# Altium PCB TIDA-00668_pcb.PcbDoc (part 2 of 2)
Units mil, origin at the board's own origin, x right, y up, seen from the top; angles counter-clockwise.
Board outline 2510.03 x 1760.03 mil, 4 copper layers (Component Side 1, Signal Layer 2, Signal Layer 3, Solder Side 4), stack 60.634 mil thick; 105 components, 46 nets, 336 pads, 4 vias.
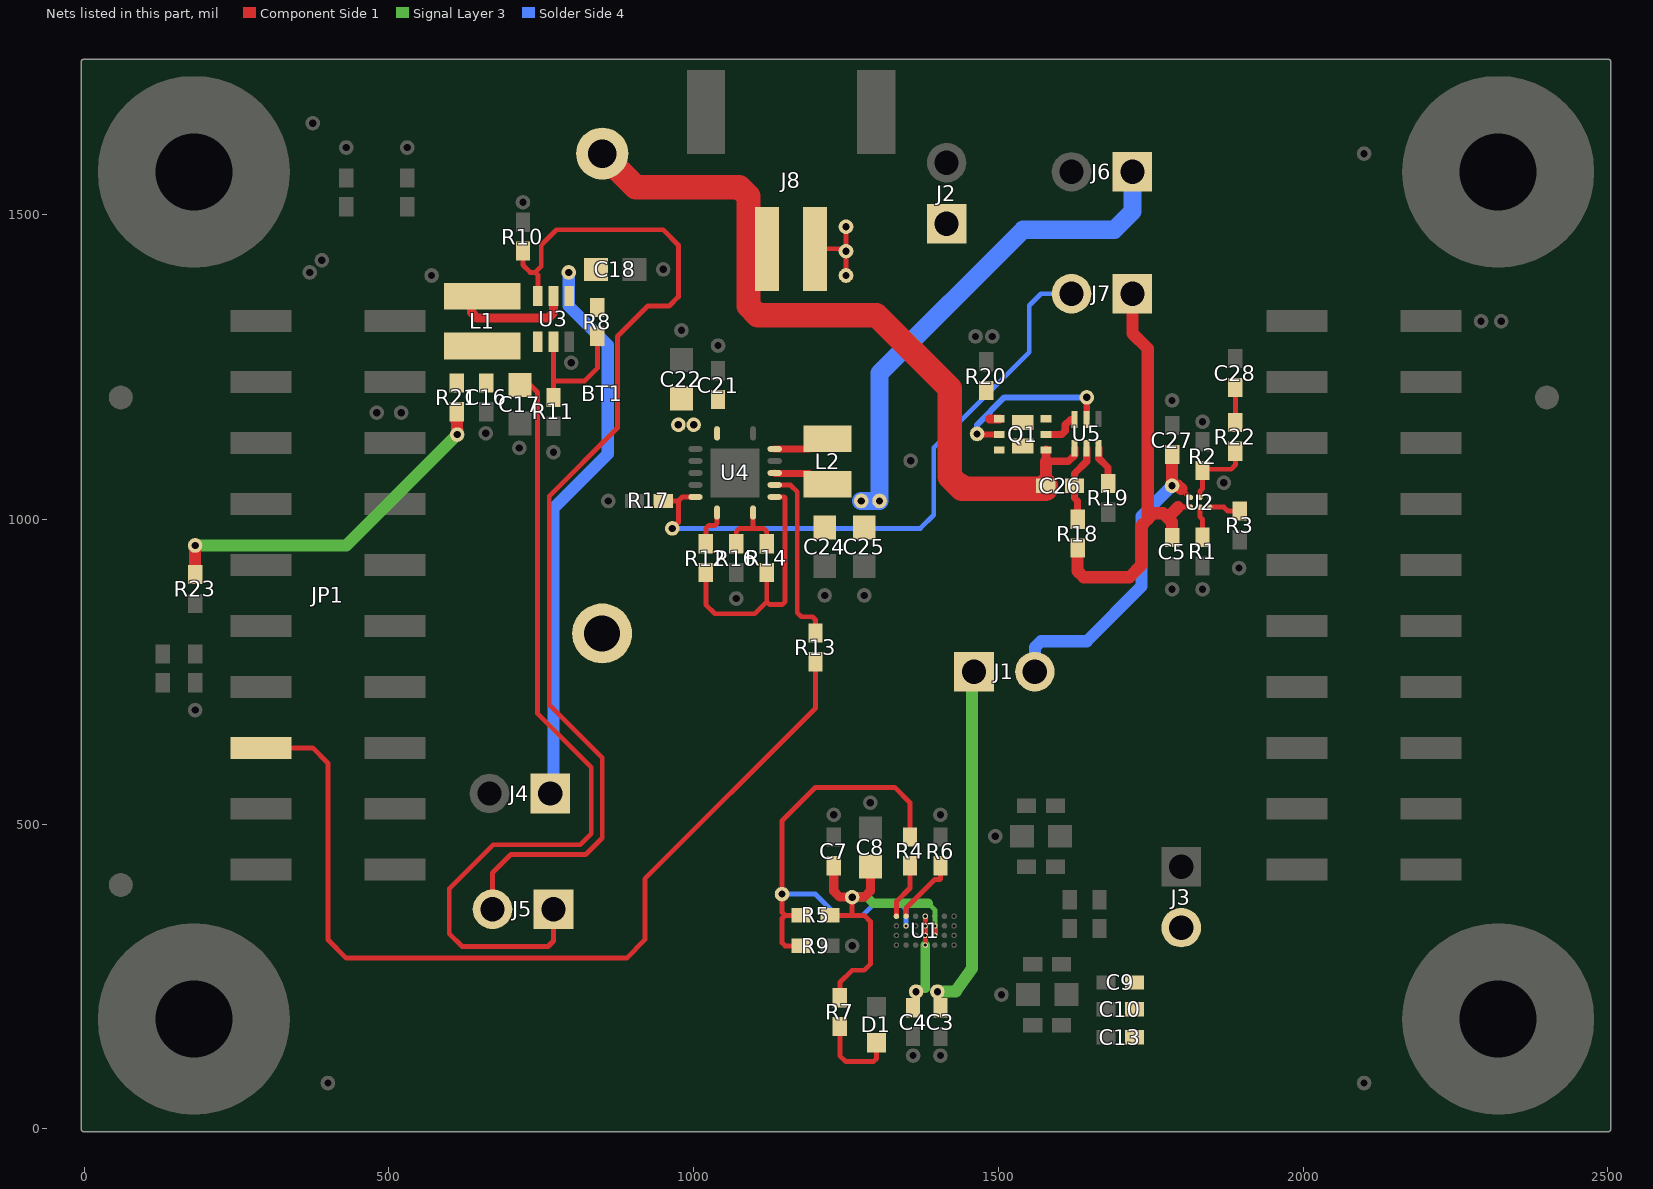
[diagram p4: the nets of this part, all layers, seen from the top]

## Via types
v1: diameter 19.68, hole 7.87, Component Side 1 to Solder Side 4, 4 vias

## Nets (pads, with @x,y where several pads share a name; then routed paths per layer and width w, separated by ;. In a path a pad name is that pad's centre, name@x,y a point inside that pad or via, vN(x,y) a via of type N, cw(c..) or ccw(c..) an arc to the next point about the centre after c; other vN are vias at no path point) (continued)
NetBT1_1: BT1.1 C5.1 C21.1 C22.1 J2.1 J7.1 J8.1 pad.0@182,957 pad.0@612,1139 pad.0@975,1155 pad.0@1000,1155 pad.0@1250,1400 pad.0@1250,1440 pad.0@1250,1480 R18.2 R21.1 R23.2 U2.A1 U4.1 | length 1457.1
  Component Side 1 w8: J8.1@1199.37,1443.86 1243.86,1443.86 pad.0@1250,1440 ; pad.0@1250,1400 pad.0@1250,1440 ; pad.0@1250,1480 pad.0@1250,1440 ; 1795,1020 U2.A1@1815,1020
  Component Side 1 w20: R23.2@182,909.24 pad.0@182,957 ; R21.1@611,1176.38 pad.0@612,1139 ; R18.2@1630,952.76 1630,915 1640,905 1715,905 1735,925 1735,990 1745,1000 ; J7.1@1720,1370 1720,1305 1745,1280 1745,1000 ; C5.1@1785,970 1785,995 1777.5,1002.5 ; 1795,1020 1777.5,1002.5 ; 1745,1000 1755,1010 1770,1010 1777.5,1002.5
  Signal Layer 3 w20: pad.0@182,957 430,957 pad.0@612,1139
NetBT1_2: BT1.2 C26.2 J8.2 Q1.4 U5.4 | length 1268.6
  Component Side 1 w12: 1578.39,1095 1615,1095 1625.32,1105.32 U5.4@1625.32,1116.38
  Component Side 1 w15: C26.2@1577.76,1055 C26.2@1578.39,1055.63 ; 1578.39,1095 Q1.4@1578.39,1113.62
  Component Side 1 w20: C26.2@1578.39,1055.63 1578.39,1095
  Component Side 1 w40: BT1.2@850,1600 905,1545 1075,1545 1090,1530 1090,1350 1105,1335 1300,1335 1420,1215 1420,1070 1439.22,1050.78 ; 1438.23,1055 1439.23,1054 ; 1440,1050 C26.2@1577.53,1050 ; C26.2@1576.76,1054 C26.2@1577.76,1055
NetC3_1: C3.1 C4.1 J1.1 pad.0@1365,225 pad.0@1380,317.13 pad.0@1380,332.9 pad.0@1380,348.65 pad.0@1380.01,301.37 pad.0@1400,225 U1.D1 U1.D2 U1.D3 U1.D4 | length 757.9
  Component Side 1 w8: U1.D4@1380,301.38 U1.D3@1380,317.13 U1.D2@1380,332.87 ; U1.D2@1380,332.87 U1.D1@1380,348.62
  Signal Layer 3 w8: pad.0@1365,225 1380,230 ; 1380,290 pad.0@1380,317.13 pad.0@1380,332.9 pad.0@1380,348.65
  Signal Layer 3 w15: 1380,230 pad.0@1380.01,301.37
  Signal Layer 3 w20: pad.0@1400,225 1430,225 1457,263 1457,747 J1.1@1460,750
NetC9_2: C9.2 C10.2 C13.2 J3.2
NetC16_1: C16.1 C17.1 J5.1 L1.1 R21.2 U3.1 | length 1374.3
  Component Side 1 w8: C17.1@715,1220.5 731.5,1220.5 744,1208 744,681 832,593 832,484 814,466 671,466 599,394 599,320 620,299 761,299 770,308 J5.1@770,360
NetC18_1: C18.1 J4.1 pad.0@795,1405 R8.2 U3.4 | length 918.4
  Solder Side 4 w20: J4.1@770,550 770,1018 859,1107 859,1286 795,1350 pad.0@795,1405
NetC24_1: C24.1 C25.1 J6.1 L2.2 pad.0@1275,1030 pad.0@1305,1030 U4.11 | length 914
  Component Side 1 w12: U4.11@1132.96,1076 1133.96,1075 1190,1075 1195,1070 L2.2@1195,1050
  Solder Side 4 w30: pad.0@1275,1030 pad.0@1305,1030 1305,1239.55 1540.45,1475 1690,1475 1720,1505 J6.1@1720,1570
NetC26_1: C26.1 R18.1 U5.5 | length 126.7
  Component Side 1 w12: R18.1@1630,1000 1630,1030 1625,1035 C26.1@1625,1055 1625,1075 1645,1095 U5.5@1645,1116.38
NetC27_1: C27.1 J1.2 pad.0@1785,1055 U2.A2 | length 536.5
  Component Side 1 w8: 1800,1050 1814.25,1035.75 U2.A2@1815,1035.75
  Component Side 1 w20: C27.1@1785,1111.38 pad.0@1785,1055 1795,1055 1800,1050
  Solder Side 4 w20: J1.2@1560,750 1560,790 1570,800 1645,800 1735,890 1735,1005 pad.0@1785,1055
NetC28_1: C28.1 R22.1 | length 57.4
  Component Side 1 w8: R22.1@1889,1159 C28.1@1889,1216.38
NetD1_1: D1.1 R7.1 | length 139.9
  Component Side 1 w8: R7.1@1240,167.76 1240,120 1250,110 1295,110 1300,115 D1.1@1300,140.94
NetJ5_2: J5.2 R10.2 U3.6 | length 1764.8
  Component Side 1 w8: J5.2@670,360 670,420 700,450 823,450 850,477 850,609 763,696 763,1038 875,1150 875,1300 925,1350 960,1350 975,1365 975,1450 950,1475 775,1475 750,1450 750,1415 740,1405 ; R10.2@720,1440 720,1417 731,1406 731,1405 740,1405 ; U3.6@744.41,1366.4 744.41,1400.59 740,1405
NetJ7_2: J7.2 pad.0@965,985 R17.2 U4.6 | length 1028.9
  Component Side 1 w8: R17.2@950,1030 975,1030 ; pad.0@965,985 975,995 975,1030 ; U4.6@1003.04,1036.63 981.63,1036.63 975,1030
  Solder Side 4 w8: pad.0@965,985 1372,985 1394,1007 1394,1117.5 1550.75,1274.25 1550.75,1350.75 1570,1370 J7.2@1620,1370
NetL1_2: L1.2 U3.5 | length 195.8
  Component Side 1 w15: L1.2@635.59,1365.76 635.59,1339.41 645,1330 761,1330 770,1339 U3.5@770,1366.4
NetL2_1: L2.1 U4.13 | length 85.5
  Component Side 1 w12: U4.13@1132.96,1115.37 1189.63,1115.37 1195,1120.73 L2.1@1195,1142
NetQ1_1: Q1.1 R20.2 | length 16.4
  Component Side 1 w15: 1485.2,1164.8 Q1.1@1501.61,1164.8
NetQ1_2: pad.0@1465,1140 pad.0@1645,1200 Q1.2 U5.2 | length 286.7
  Component Side 1 w10: pad.0@1465,1140 1474.21,1139.21 Q1.2@1501.61,1139.21 ; U5.2@1645,1163.62 pad.0@1645,1200
  Solder Side 4 w10: pad.0@1465,1140 1465,1155 1510,1200 pad.0@1645,1200
NetQ1_3: Q1.3 Q1.6 Q1.7 Q1.8
NetQ1_5: Q1.5 U5.3 | length 56.2
  Component Side 1 w12: Q1.5@1578.39,1139.21 1604.21,1139.21 1610,1145 1610,1155 1618.62,1163.62
NetR1_2: R1.2 U2.B1 | length 51.8
  Component Side 1 w8: U2.B1@1830.75,1020 1830.75,1004.25 1835,1000 R1.2@1835,970
NetR2_2: R2.2 R22.2 U2.B2 | length 127.7
  Component Side 1 w8: U2.B2@1830.75,1035.75 1830.75,1045.75 1835,1050 R2.2@1835,1080 1835,1082 1882,1082 1889,1089 R22.2@1889,1111.76
NetR3_2: R3.2 U2.C1 | length 51.1
  Component Side 1 w8: U2.C1@1846.5,1020 1870,1020 1876.38,1013.62 R3.2@1895,1013.62
NetR4_1: pad.0@1145,385 pad.0@1348.5,332.85 R4.1 R5.1 R9.2 U1.F2 | length 819
  Component Side 1 w8: R9.2@1176.38,300 1150,300 1145,305 1145,345 1150,350 ; R5.1@1176.38,350 1150,350 ; R4.1@1355,478.62 1355,535 1330,560 1200,560 1145,505 pad.0@1145,385 1145,355 1150,350
  Solder Side 4 w8: pad.0@1145,385 1200,385 1235,350 1277.5,350 1295,367.5 1341,367.5 1348.5,360 pad.0@1348.5,332.85
NetR4_2: R4.2 U1.G1 | length 92
  Component Side 1 w8: U1.G1@1332.76,348.62 1332.76,372.76 1355,395 R4.2@1355,431.38
NetR8_1: R8.1 R11.2 U3.2 | length 224.7
  Component Side 1 w8: R11.2@770,1200 770,1227 ; U3.2@770,1291.6 770,1227 ; R8.1@842,1300.38 842,1248 821,1227 770,1227
NetR12_1: R12.1 R14.2 U4.9 | length 436.9
  Component Side 1 w8: R12.1@1020,912.76 1020,860 1035,845 1100,845 1120,865 ; R14.2@1120,912.76 1120,865 ; U4.9@1132.96,1036.63 1148.37,1036.63 1150,1035 1150,865 1145,860 1125,860 1120,865
NetR12_2: R12.2 U4.7 | length 64.5
  Component Side 1 w8: R12.2@1020,960 1020,985 1025,990 1035,990 1038.47,993.47 U4.7@1038.47,1011.04
NetR13_2: R13.2 U4.10 | length 296.1
  Component Side 1 w8: U4.10@1132.96,1056.31 1158.69,1056.31 1170,1045 1170,846.93 1176.93,840 1195,840 1200,835 R13.2@1200,813.62
NetR14_1: R14.1 R16.2 U4.8 | length 117.7
  Component Side 1 w8: R16.2@1070,960 1070,980 1075,985 1115,985 1120,980 R14.1@1120,960 ; 1097.52,987.52 U4.8@1097.52,1011.04
NetR19_2: R19.2 U5.6 | length 64.1
  Component Side 1 w12: U5.6@1664.68,1116.38 1664.68,1100.32 1680,1085 R19.2@1680,1058.62
RECT: C7.1 C8.1 pad.0@1260,380 pad.0@1395.75,317.1 pad.0@1395.75,332.85 R5.2 R7.2 U1.C2 U1.C3 | length 609.9
  Component Side 1 w8: R5.2@1223.62,350 1260,350 ; R7.2@1240,215 1240,240 1260,260 1280,260 1290,270 1290,340 1280,350 1260,350 ; pad.0@1260,380 1260,350 ; U1.C3@1395.75,317.13 U1.C2@1395.75,332.87
  Component Side 1 w15: C7.1@1230,431.38 1230,390 1240,380 pad.0@1260,380 1280,380 1290,390 C8.1@1290,430
  Signal Layer 3 w8: 1385,370 1395.75,359.25 pad.0@1395.75,332.85 pad.0@1395.75,317.1
  Signal Layer 3 w15: pad.0@1260,380 1285,380 1295,370 1385,370
TS: R6.2 U1.F1 | length 110.9
  Component Side 1 w8: U1.F1@1348.5,348.62 1348.5,361.61 1396.05,409.15 1404.15,409.15 1405,410 R6.2@1405,431.38
VIN_OK: JP1.15 R13.1 | length 1527.6
  Component Side 1 w8: JP1.15@290,625 375,625 400,600 400,310 430,280 890,280 920,310 920,410 1200,690 R13.1@1200,766.38
pads on no net: FID1.1 FID2.1 FID3.1 H1.1 H2.1 H3.1 H4.1 H5.1 H6.1 H7.1 H8.1 HS5.0 HS6.0 HS7.0 HS8.0 J8.M1 J8.M2 JP1.3 JP1.5 JP1.6 JP1.7 JP1.8 JP1.9 JP1.10 JP1.12 JP1.13 JP1.14 JP1.16 JP1.17 JP1.18 JP1.19 JP1.20 JP2.1 JP2.3 JP2.4 JP2.5 JP2.6 JP2.7 JP2.8 JP2.9 JP2.10 JP2.11 JP2.12 JP2.13 JP2.14 JP2.15 JP2.16 JP2.17 JP2.18 JP2.19 JP2.20 SH-J1.0 SH-J4.0 SH-J5.0 SH-J6.0 SH-J7.0 U1.F3 U4.2 U4.3 U4.4 U4.14 U5.1

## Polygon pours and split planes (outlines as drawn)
GND on Signal Layer 2 "Signal Layer 2-GND" (solid, remove dead copper, pour order 2): 25,25 25,1725 2475,1725 2475,25 25,25
GND on Signal Layer 3 "Signal Layer 3-gnd" (solid, remove dead copper, pour order 8): 25,25 2475,25 2475,1725 25,1725 25,25
NetBT1_1 on Signal Layer 3 "Signal Layer 3-BT1_1" (solid, remove dead copper, pour order 4): 1800,1625 575,1625 575,275 925,275 925,550 1050,675 1800,675 1800,1625
GND on Component Side 1 "Component Side 1-gnd" (solid, remove dead copper, pour order 6): 25,25 2475,25 2475,1725 25,1725 25,25
GND on Solder Side 4 "Solder Side 4-gnd" (solid, remove dead copper, pour order 10): 2475,25 2475,1725 25,1725 25,25

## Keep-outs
Keep-Out Layer:
  lines w10: 0,0 2500,0 ; 0,0 0,1750 ; 0,0 2500,0 ; 0,1750 2500,1750 ; 0,1750 2500,1750 ; 2500,0 2500,1750 ; 2500,0 2500,1750
  text ".Layer_Name" at 577,-858.49 h60

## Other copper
Component Side 1:
  rectangle net GND: 787,1242 819,1310
  rectangle net NetC16_1: 590,1208 744,1309
  rectangle net NetQ1_5: 1604,1150 1630,1178
  rectangle net NetBT1_2: 1568,1044 1597,1121
  rectangle net GND: 1441.78,1245 1515,1325
  rectangle net NetQ1_1: 1465,1160 1510,1225
  rectangle net NetQ1_3: 1550,1160 1595,1235
  rectangle net NetQ1_3: 1450,1080 1525,1120
  rectangle net NetQ1_3: 1520,1080 1560,1235
  rectangle net NetL1_2: 592,1323 727,1388
  rectangle net NetBT1_1: 1180,1375 1275,1515
  rectangle net NetBT1_2: 1035,1375 1135,1515
  rectangle net NetC24_1: 1180,965 1355,1057.45
  rectangle net GND: 1190,850 1350,940
  rectangle net NetC18_1: 788,1355 860,1425
  rectangle net NetBT1_1: 960,1140 1055,1220
  rectangle net GND: 1350,110 1415,165
  rectangle net NetC3_1: 1350,185 1415,240
  rectangle net AC1: 1590,130 1690,345
  rectangle net NetC9_2: 1765,215 1835,360
  rectangle net NetC9_2: 1710,125 1835,265
  rectangle net AC2: 1700,395 1840,465
  rectangle net AC2: 1580,360 1720,550
  text "TI" at 2440,896 h60 r90
  text ".CopyrightYear" at 2440,620 h60 r90
  text "©" at 2445,510 h105 r90
  text ".Layer_Name" at 577,-858.49 h60
Signal Layer 3:
  rectangle net GND: 1350,110 1415,135
  rectangle net NetC3_1: 1350,215 1415,240
Solder Side 4:
  text "MADE IN U.S." at 300,1180 h60 r90
  text "UL94V-0" at 420,1100 h60 r90
  text ".Layer_Name" at 577,-858.49 h60

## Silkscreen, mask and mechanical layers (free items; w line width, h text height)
Top Overlay:
  lines w7: 1849,1306 1868.5,1288
  lines w10: 576,1445 576,1036 640,990 780,990 820,1030 820,1150 870,1200 870,1320 900,1350 940,1350 950,1360 950,1480 900,1530 810,1530 770,1570 770,1630 760,1640 630,1640 590,1600 590,1460 576,1446 577,1447 ; 1735,1297 1735,835 1780,790 1860,790 1924,854 1923,1286 ; 850,1000 960,890 960,795 1035,720 1370,720 1370,790 1430,850 1450,870 1450,1015 1410,1055 1325,1055 1290,1090 1290,1280 1280,1290 1095,1290 1065,1320 930,1320 910,1320 890,1300 890,1160 850,1120 850,1000 ; 1066,184 1066,389 1100,423 1100,540 1170,610 1820,610 1920,510 1920,140 1884,90 1160,90 1100,150 1066,184 ; 1430,1095 1475,1050 1475,945 1555,865 1695,865 1710,880 1710,1230 1630,1310 1600,1310 1475,1310 1430,1270 1430,1095
  text "J6=3.3V CONNECT" at 1570,1640 h40
  text "+BAT-" at 1520,1440 h40 r90
  text "J7=3.3V ENABLE" at 1560,1440 h40
  text "3.3V Buck" at 1100,1300 h40
  text ".PCB_Rev" at 92,1087 h60 r90
  text "5V Boost" at 574,938 h40
  text "Prot" at 1578,816 h40
  text "Charger" at 1659,750 h40
  text "Current" at 1615,675 h40
  text "J4=5V CONNECT" at 600,625 h40
  text "Shunt" at 1615,625 h40
  text ".PRJ_Number" at 89,477 h60 r90
  text "J5=5V ENABLE" at 600,425 h40
  text "COIL" at 1900,317 h40 r90
  text "Wireless RX" at 1645,40 h40
  text ".Layer_Name" at 577,-858.49 h60
Bottom Overlay:
  text ".Layer_Name" at 577,-858.49 h60
Top Paste:
  text ".Layer_Name" at 577,-858.49 h60
Bottom Paste:
  text ".Layer_Name" at 577,-858.49 h60
Top Solder:
  text ".Layer_Name" at 577,-858.49 h60
  text ".Layer_Name" at 577,-858.49 h60
Bottom Solder:
  text ".Layer_Name" at 577,-858.49 h60
Drill Guide:
  text ".Layer_Name" at 577,-858.49 h60
Mechanical 1:
  lines w10: 0,0 2500,0 2500,1750 0,1750 0,0
  text ".Layer_Name" at 577,-858.49 h60
Mechanical 2:
  rectangle: 0,-275 125,-150
  rectangle: 125,-400 500,-275
  lines w7: 0,-275 1000,-275 ; 125,-400 125,-150 ; 250,-400 250,-150 ; 500,-400 500,-150 ; 750,-400 750,-150 ; 0,-400 1000,-400 1000,-150 0,-150 0,-400
  text ".Layer_Name" at 577,-858.49 h60
Mechanical 3:
  text "Jumpers" at -15,3205 h40
  text "Mounting holes in the coil boards" at 1445,2685 h40
  text "Spacers" at -15,2635 h40
  text ".Layer_Name" at 577,-858.49 h60
Mechanical 4:
  text ".Layer_Name" at 577,-858.49 h60
Mechanical 5:
  lines w10: -292,-930.17 6308,-930.17 ; -292,-726.83 6310,-726.83 ; -292,-523.5 -292,-1133.5 3713,-1133.5 6310,-1133.5 6310,-523.5 -291.5,-523.5 -291.5,-1133.5 1284,-1133.5 ; 2173,-1133.5 2173,-523.5 ; 3440,-726.83 3440,-523.5 ; 4280,-726.83 4280,-523.5 ; 4902,-1140 4902,-937.17
  text "COMPONENTS MARKED 'DNP' SHOULD NOT BE POPULATED." at 1153.5,-318.5 h60
  text "ASSEMBLY VARIANT:" at 1153,-434 h60
  text ".VariantName" at 2189,-434 h60
  text "PCB VIEWED FROM TOP SIDE" at -228.5,-655.67 h60
  text "BOARD #:" at 2248,-655.67 h60
  text ".PRJ_Number" at 2793.5,-655.67 h60
  text "REV:" at 3638,-655.67 h60
  text ".PCB_Rev" at 3929.5,-655.67 h60
  text "SVN REV:" at 4476,-655.67 h60
  text ".VersionControl_RevNumber" at 4982,-655.67 h60
  text "PLOT NAME =" at -228.5,-1064.34 h60
  text ".plot_File_Name" at 577,-1064.34 h60
  text "GENERATED    :" at 2250,-1064.34 h60
  text ".Print_Date" at 3119.5,-1064.34 h60
  text ".Print_Time" at 3848.5,-1064.34 h60
  text "TEXAS INSTRUMENTS" at 5113,-1064.34 h60
Mechanical 6:
  lines w10: -292.5,-727.33 6309.5,-727.33 ; -290.5,-930.67 6309.5,-930.67 ; 1115.5,-1140.5 1115.5,-937.67 ; 1737.5,-727.33 1737.5,-524 ; 2577.5,-727.33 2577.5,-524 ; 3844.5,-1134 3844.5,-524 ; 4733.5,-1134 6309,-1134 6309,-524 -292.5,-524 -292.5,-1134 2304.5,-1134 6309.5,-1134 6309.5,-524
  text "COMPONENTS MARKED 'DNP' SHOULD NOT BE POPULATED." at 6102,-318 h60
  text ".VariantName" at 5058,-434 h60
  text "ASSEMBLY VARIANT:" at 6097,-434 h60
  text ".VersionControl_RevNumber" at 1035.5,-656.17 h60
  text "SVN REV:" at 1541.5,-656.17 h60
  text ".PCB_Rev" at 2088,-656.17 h60
  text "REV:" at 2379.5,-656.17 h60
  text ".PRJ_Number" at 3224,-656.17 h60
  text "BOARD #:" at 3769.5,-656.17 h60
  text "PCB VIEWED FROM BOTTOM SIDE" at 6246,-656.17 h60
  text "TEXAS INSTRUMENTS" at 904.5,-1064.84 h60
  text ".Print_Time" at 2169,-1064.84 h60
  text ".Print_Date" at 2898,-1064.84 h60
  text "GENERATED    :" at 3767.5,-1064.84 h60
  text ".plot_File_Name" at 5440.5,-1064.84 h60
  text "PLOT NAME =" at 6246,-1064.84 h60
Mechanical 9:
  drawing of 57 lines, arcs and shapes, not listed
  text "1" at 739.84,8036.5 h70
  text "2" at 3235.5,8036.5 h70
  text "3" at 5724.84,8036.5 h70
  text "4" at 8231.51,8036.5 h70
  text "5" at 10730.5,8036.5 h70
  text "6" at 13235.5,8036.5 h70
  text "A" at -416.5,6893.5 h70
  text "A" at 14383.5,6893.5 h70
  text "B" at -416.5,4513.5 h70
  text "B" at 14383.5,4513.5 h70
  text "C" at -416.5,2138.5 h70
  text "C" at 14383.5,2138.5 h70
  text "PROJECT TITLE:" at 11343.5,277.5 h45
  text ".PRJ_Title" at 11393.5,144.17 h70
  text "DESIGNED FOR:" at 11343.5,-23.5 h45
  text ".PRJ_Customer" at 11393.5,-163.5 h70
  text "D" at -416.5,-231.5 h70
  text "D" at 14383.5,-231.5 h70
  text "FILE NAME:" at 11343.5,-323.5 h45
  text ".PCB_File_Name_No_Path" at 11393.5,-443.5 h70
  text "Texas Instruments (TI) and/or its licensors do not warrant the accuracy or completeness of this specification" at 6374,-605.34 h45
  text "ENGINEER:" at 11343.5,-613.5 h45
  text "LAYOUT BY:" at 12848.5,-613.5 h45
  text "or any information contained therein. TI and/or its licensors do not warrant that this design will meet" at 6329.01,-718 h45
  text ".PRJ_Engineer" at 11393.5,-768.49 h70
  text ".PCB_Layout" at 12899,-768.49 h70
  text "the specifications, will be suitable for your application or fit for any particular purpose, or will operate in" at 6329.01,-830.67 h45
  text ".Layer_Name" at 577,-858.49 h60
  text "ALTIUM DESIGNER VERSION:" at 12848.5,-923.5 h45
  text "an implementation. TI and/or its licensors do not warrant that the design is production worthy. You should" at 6329.01,-943.33 h45
  text "completely validate and test your design implementation to confirm the system functionality for your application." at 6374,-1056 h45
  text ".print_Scale" at 11393.5,-1056.83 h70
  text ".Application_BuildNumber" at 12899,-1056.83 h70
  text "1" at 739.84,-1263.5 h70
  text "2" at 3235.5,-1263.5 h70
  text "3" at 5724.84,-1263.5 h70
  text "4" at 8231.51,-1263.5 h70
  text "5" at 10730.5,-1263.5 h70
  text "6" at 13235.5,-1263.5 h70
Mechanical 10:
  drawing of 185 lines, arcs and shapes, not listed
  text "DESIGN INFORMATION" at 12381.02,5910 h60
  text "MIN. TRACK WIDTH:" at 11736.46,5730 h60
  text "6" at 12832.7,5730 h60
  text "MIL" at 12987.46,5730 h60
  text "6" at 12820,5600 h60
  text "MIN. CLEARANCE:" at 11736.46,5598 h60
  text "MIL" at 12987.46,5598 h60
  text "MIN. VIA PAD SIZE:" at 11736.46,5466 h60
  text "9" at 12802.71,5466 h60
  text "MIL" at 12987.46,5466 h60
  text "0.05mm (2MIL)" at 12431.46,5324.29 h60
  text "MINIMUM ANNULAR RING" at 11407.23,5320 h60
  text "EXTERNAL" at 13139.46,5320 h60
  text "PER" at 11607.23,5202 h60
  text "IPC-D-275 CLASS 2 LEVEL C" at 11827.23,5202 h60
  text "MIL, HOLES" at 13315.46,5089.71 h60
  text "+/-" at 12923,5089 h60
  text "+/-" at 13777,5089 h60
  text "REGISTRATION TOLERANCES:" at 11407.23,5084 h60
  text "METAL" at 12607,5084 h60
  text "5" at 13183.2,5084 h60
  text "1" at 14016.2,5084 h60
  text "MIL" at 14132.46,5084 h60
  text "MATERIAL:" at 11332.46,4874.54 h60
  text "FR-4 High Tg" at 12318.9,4734.21 h60
  text "FR-408" at 11753.46,4725.64 h60
  text "X" at 12165.46,4725.64 h60
  text "OTHER" at 13241.46,4725.64 h60
  text "62 MIL (1.6mm) +/-10%" at 12073.56,4562.92 h60
  text "THICKNESS:" at 11407.23,4558.64 h60
  text "X" at 11945.4,4558.64 h60
  text "OTHER" at 13358.46,4558.64 h60
  text "TOLERANCE:" at 11407.23,4400.64 h60
  text "X" at 12246.53,4400.64 h60
  text "ANSI IPC-6012 TYPE 3 CLASS 2" at 12433.48,4400.64 h60
  text "OTHER +/-" at 12433.46,4244.64 h60
  text "BOW & TWIST:" at 11407.23,4087.64 h60
  text "X" at 12246.53,4087.64 h60
  text "ANSI IPC-6012 TYPE 3 CLASS 2" at 12433.48,4087.64 h60
  text "OTHER +/-" at 12433.46,3929.13 h60
  text "DRILLING:" at 11332.46,3790.64 h60
  text "REFERENCE:" at 11407.23,3673.64 h60
  text "X" at 12055.46,3673.64 h60
  text "AS SHOWN" at 12242.46,3673.64 h60
  text "X" at 12956.46,3673.64 h60
  text "NC_DRILL FILES" at 13093.46,3673.64 h60
  text "PTH MIN COPPER THICKNESS:" at 11407.23,3515.64 h60
  text "X" at 12757.46,3515.64 h60
  text "1MIL" at 12894.46,3515.64 h60
  text "OTHER" at 13391.46,3515.64 h60
  text "BOARD FINISH:" at 11332.46,3356.64 h60
  text "SILKSCREEN:" at 11487.68,3238.64 h60
  text "X" at 12436.46,3238.64 h60
  text "TOP" at 12562.46,3238.64 h60
  text "X" at 12946.46,3238.64 h60
  text "BOTTOM" at 13073.46,3238.64 h60
  text "SILKSCREEN COLOR:" at 11487.68,3071.64 h60
  text "X" at 12435.42,3071.64 h60
  text "WHITE" at 12562.46,3071.64 h60
  text "OTHER" at 13073.46,3071.64 h60
  text "SOLDER RESIST COLOR:" at 11487.68,2901.64 h60
  text "X" at 13160,2745 h60
  text "GREEN" at 12182.46,2742.44 h60
  text "BLUE" at 12773.46,2742.44 h60
  text "OTHER" at 13311.46,2742.44 h60
  text "RED" at 13671.46,2742.44 h60
  text "IMMERSION GOLD (ENIG)" at 12393.46,2553.92 h60
  text "ENEPIG" at 13731,2550.64 h60
  text "SURFACE FINISH:" at 11332.46,2549.64 h60
  text "X" at 12206.51,2549.64 h60
  text "IMM. TIN/SILVER OR EQUIV" at 11662,2392.64 h60
  text "OTHER" at 13093.46,2392.64 h60
  text "ARRAY/PANEL:" at 11332.46,2213.64 h60
  text "CUT AND TRIM PER MECH LAYER 1" at 12393.46,2209.35 h60
  text "N.C. ROUTE" at 12393.46,2057.64 h60
  text "X" at 13072.46,2057.64 h60
  text "V. SCORE" at 13259.46,2057.64 h60
  text "CERTIFICATION:" at 11332.46,1920.64 h60
  text "MATERIALS AND WORKMANSHIP FOR ALL PCBS" at 12057.46,1920.64 h60
  text "TO MEET OR EXCEED THE REQUIREMENTS OF:" at 12057.46,1822.64 h60
  text "X" at 11683.96,1686.13 h60
  text "ANSI IPC-A-600F CLASS ->" at 11822.96,1686.13 h60
  text "X" at 13462.02,1686.13 h60
  text "2" at 13580.96,1686.14 h60
  text "1" at 13265.96,1684.64 h60
  text "3" at 13934.96,1684.64 h60
  text "X" at 11686.02,1526.64 h60
  text "UL 94V-0" at 11822.96,1526.64 h60
  text "X" at 12498.02,1526.64 h60
  text "RoHS" at 12634.96,1526.64 h60
  text "OTHER" at 13279.36,1526.64 h60
  text "PER ORDER" at 13676.42,1526.64 h60
  text "ADDITIONAL REQUIREMENTS:" at 11332.46,1385.64 h60
  text "MICROSECTION:" at 11407.23,1270.64 h60
  text "YES" at 12312.96,1270.64 h60
  text "REQUIRED" at 13174.46,1114.49 h60
  text "BARE BOARD ELEC. TEST:" at 11407.23,1111.64 h60
  text "NONE" at 12712.96,1111.64 h60
  text "X" at 13047.46,1111.64 h60
  text "PER ORDER" at 13766.46,1111.64 h60
  text "MANUFACTURER'S UL:" at 11407.23,954.64 h60
  text "RAIL" at 12572.96,950.35 h60
  text "METAL" at 13064.77,950.35 h60
  text "X" at 13440,950 h60
  text "SILK" at 13576.46,950.35 h60
  text ".Layer_Name" at 577,-858.49 h60
Mechanical 11:
  lines w10: -292,-930.17 6308,-930.17 ; -292,-726.83 6310,-726.83 ; -292,-523.5 -292,-1133.5 3713,-1133.5 6310,-1133.5 6310,-523.5 -291.5,-523.5 -291.5,-1133.5 1284,-1133.5 ; 2173,-1133.5 2173,-523.5 ; 3440,-726.83 3440,-523.5 ; 4280,-726.83 4280,-523.5 ; 4902,-1140 4902,-937.17
  text "ALL ARTWORK VIEWED FROM TOP SIDE" at -228.5,-655.67 h60
  text "BOARD #:" at 2248,-655.67 h60
  text ".PRJ_Number" at 2793.5,-655.67 h60
  text "REV:" at 3638,-655.67 h60
  text ".PCB_Rev" at 3929.5,-655.67 h60
  text "SVN REV:" at 4476,-655.67 h60
  text ".VersionControl_RevNumber" at 4982,-655.67 h60
  text "LAYER NAME =" at -228.5,-858.49 h60
  text "PLOT NAME =" at -228.5,-1064.34 h60
  text ".plot_File_Name" at 577,-1064.34 h60
  text "GENERATED    :" at 2250,-1064.34 h60
  text ".Print_Date" at 3119.5,-1064.34 h60
  text ".Print_Time" at 3848.5,-1064.34 h60
  text "TEXAS INSTRUMENTS" at 5113,-1064.34 h60
Mechanical 12:
  text ".Layer_Name" at 577,-858.49 h60
Mechanical 13:
  text "The ferrite shield will be cut to fit the PCB dimensions" at -25,7500 h40
  text "4 holes will be added to match the four mounting holes only" at -25,7425 h40
  text "Coil 1 is added to PCB C02 with double stick tape and the wires are soldered to the PCB" at -50,6225 h40
  text ".Layer_Name" at 577,-858.49 h60
Mechanical 14:
  text ".Layer_Name" at 577,-858.49 h60
Mechanical 15:
  text ".Layer_Name" at 577,-858.49 h60
Mechanical 16:
  text ".Layer_Name" at 577,-858.49 h60
Drill Drawing:
  drawing of 361 lines, arcs and shapes, not listed
  text "Layer" at 9670.38,7805 h60
  text "Name" at 10080.29,7805 h60
  text "Material" at 11120,7805 h60
  text "Thickness" at 11979.77,7805 h60
  text "Constant" at 12629.6,7805 h60
  text "Board Layer Stack" at 13199.46,7805 h60
  text "1" at 9670.38,7685 h60
  text "Top Overlay" at 10080.29,7685 h60
  text "2" at 9670.38,7565 h60
  text "Top Solder" at 10080.29,7565 h60
  text "Solder Resist" at 11120,7565 h60
  text "0.40mil" at 11979.77,7565 h60
  text "3.5" at 12629.6,7565 h60
  text "3" at 9670.38,7445 h60
  text "Component Side 1" at 10080.29,7445 h60
  text "Copper" at 11120,7445 h60
  text "1.40mil" at 11979.77,7445 h60
  text "4" at 9670.38,7325 h60
  text "Dielectric 1" at 10080.29,7325 h60
  text "FR-4HT" at 11120,7325 h60
  text "10.00mil" at 11979.77,7325 h60
  text "4.2" at 12629.6,7325 h60
  text "5" at 9670.38,7205 h60
  text "Signal Layer 2" at 10080.29,7205 h60
  text "Copper" at 11120,7205 h60
  text "1.42mil" at 11979.77,7205 h60
  text "6" at 9670.38,7085 h60
  text "Dielectric 2" at 10080.29,7085 h60
  text "35.00mil" at 11979.77,7085 h60
  text "4.2" at 12629.6,7085 h60
  text "7" at 9670.38,6965 h60
  text "Signal Layer 3" at 10080.29,6965 h60
  text "Copper" at 11120,6965 h60
  text "1.42mil" at 11979.77,6965 h60
  text "8" at 9670.38,6845 h60
  text "Dielectric 3" at 10080.29,6845 h60
  text "FR-4HT" at 11120,6845 h60
  text "10.00mil" at 11979.77,6845 h60
  text "4.2" at 12629.6,6845 h60
  text "9" at 9670.38,6725 h60
  text "Solder Side 4" at 10080.29,6725 h60
  text "Copper" at 11120,6725 h60
  text "1.40mil" at 11979.77,6725 h60
  text "10" at 9670.38,6605 h60
  text "Bottom Solder" at 10080.29,6605 h60
  text "Solder Resist" at 11120,6605 h60
  text "0.40mil" at 11979.77,6605 h60
  text "3.5" at 12629.6,6605 h60
  text "11" at 9670.38,6485 h60
  text "Bottom Overlay" at 10080.29,6485 h60
  text "Symbol" at 5569.7,3345.35 h72
  text "Quantity" at 5895.36,3345.35 h72
  text "Finished Hole Size" at 6252.52,3345.35 h72
  text "Plated" at 6914,3345.35 h72
  text "Hole Type" at 7198.2,3345.35 h72
  text "16" at 5895.36,3195.85 h60
  text "5.00mil (0.127mm)" at 6252.52,3195.85 h60
  text "PTH" at 6914,3195.85 h60
  text "Round" at 7198.2,3195.85 h60
  text "4" at 5895.36,3046.35 h60
  text "7.87mil (0.200mm)" at 6252.52,3046.35 h60
  text "PTH" at 6914,3046.35 h60
  text "Round" at 7198.2,3046.35 h60
  text "61" at 5895.36,2896.85 h60
  text "12.00mil (0.305mm)" at 6252.52,2896.85 h60
  text "PTH" at 6914,2896.85 h60
  text "Round" at 7198.2,2896.85 h60
  text "14" at 5895.36,2747.35 h60
  text "40.00mil (1.016mm)" at 6252.52,2747.35 h60
  text "PTH" at 6914,2747.35 h60
  text "Round" at 7198.2,2747.35 h60
  text "1" at 5895.36,2597.85 h60
  text "46.50mil (1.181mm)" at 6252.52,2597.85 h60
  text "PTH" at 6914,2597.85 h60
  text "Round" at 7198.2,2597.85 h60
  text "1" at 5895.36,2448.35 h60
  text "59.06mil (1.500mm)" at 6252.52,2448.35 h60
  text "PTH" at 6914,2448.35 h60
  text "Round" at 7198.2,2448.35 h60
  text "8" at 5895.36,2298.85 h60
  text "125.98mil (3.200mm)" at 6252.52,2298.85 h60
  text "PTH" at 6914,2298.85 h60
  text "Round" at 7198.2,2298.85 h60
  text "105 Total" at 5895.36,2149.35 h60
  text ".Layer_Name" at 577,-858.49 h60

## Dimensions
0,-400 to 1000,-400 on Mechanical 2
0,0 to 2500,0 on Component Side 1
0,1750 to 0,0 on Component Side 1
